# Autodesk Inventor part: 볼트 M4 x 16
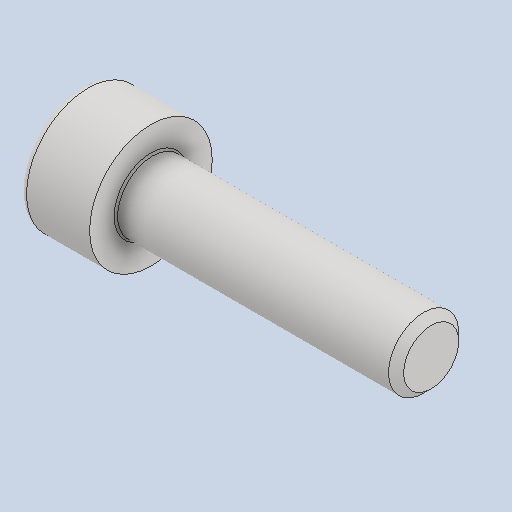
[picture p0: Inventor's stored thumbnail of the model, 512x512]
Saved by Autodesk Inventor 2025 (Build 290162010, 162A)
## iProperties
Created: 2024-07
Part Number: 볼트 M4 x 16
Material: 스테인리스강
Description: 6각 소켓 머리 캡 나사
Document SubType Name: Modeling
Designer: 학생
Density: 8.08 g/cm^3
Appearance: 기본값
Author: jhkim
Sending System: Autodesk Inventor 2025
Preprocessor: ST-DEVELOPER v20
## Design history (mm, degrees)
feature "Solid1"
node "솔리드1"
